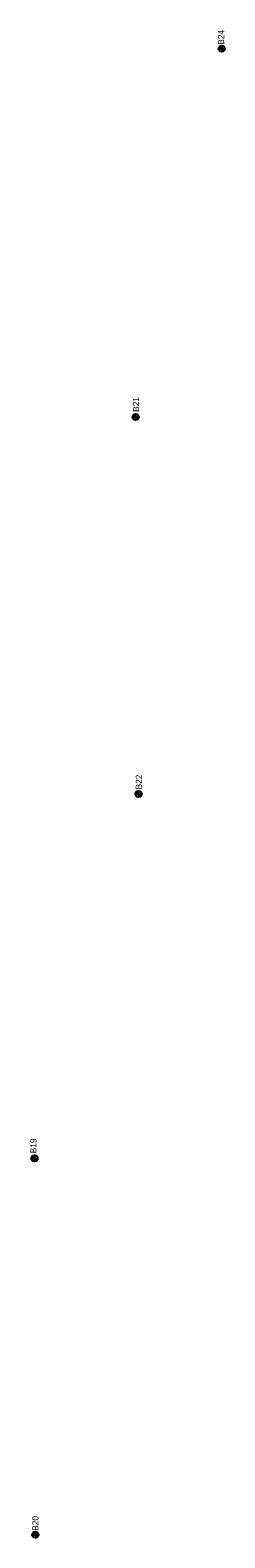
# Model space of a CAD drawing. Extents: x 331323 to 388339, y 121519 to 205315.
# Drawn here: x 361288 to 361600, y 138551 to 140969 of the extents above; entities that cross this region are included whole.
import ezdxf

# ---------------------------------------------------------------- set-up
doc = ezdxf.new("R2010")
doc.units = 0
for name, color, linetype in [('E_SOIL_BORE1 [KAPUR_CADDS_LEVELS]', 7, 'Continuous'), ('E_SOIL_BORE2 [KAPUR_CADDS_LEVELS]', 7, 'Continuous'), ('P_MARK', 7, 'Continuous')]:
    doc.layers.add(name, color=color, linetype=linetype)

msp = doc.modelspace()

# ---------------------------------------------------------------- linework, layer by layer
at = {"layer": 'P_MARK'}
for p, q in [((361590.2, 140939.4), (361600.2, 140939.3)), ((361595.2, 140944.3), (361595.2, 140934.4)), ((361452.1, 140348.7), (361462, 140348.7)), ((361457.1, 140353.7), (361457, 140343.7)), ((361456.7, 139744.2), (361466.7, 139744.2)), ((361461.7, 139749.2), (361461.7, 139739.2)), ((361289.9, 139159.7), (361299.9, 139159.7)), ((361294.9, 139164.7), (361294.9, 139154.7)), ((361291.3, 138556.1), (361301.3, 138556.1)), ((361296.3, 138561.1), (361296.3, 138551.1))]:
    msp.add_line(p, q, dxfattribs=at)
for centre in [(361595.2, 140939.4), (361457.1, 140348.7), (361461.7, 139744.2), (361294.9, 139159.7), (361296.3, 138556.1)]:
    msp.add_circle(centre, 5, dxfattribs=at)
for centre, radius, start, end in [((361595.2, 140939.4), 4.5, 89.9869, 179.9869), ((361595.2, 140939.4), 4, 89.9869, 179.9869), ((361595.2, 140939.4), 3.5, 89.9869, 179.9869), ((361595.2, 140939.4), 3, 89.9869, 179.9869), ((361595.2, 140939.4), 2.5, 89.9869, 179.9869), ((361595.2, 140939.4), 2, 89.9869, 179.9869), ((361595.2, 140939.4), 1.5, 89.9869, 179.9869), ((361595.2, 140939.4), 1, 89.9869, 179.9869), ((361595.2, 140939.4), 0.5, 89.9869, 179.9869), ((361595.2, 140939.4), 4.5, 269.9869, 359.9869), ((361595.2, 140939.4), 4, 269.9869, 359.9869), ((361595.2, 140939.4), 3.5, 269.9869, 359.9869), ((361595.2, 140939.4), 3, 269.9869, 359.9869), ((361595.2, 140939.4), 2.5, 269.9869, 359.9869), ((361595.2, 140939.4), 2, 269.9869, 359.9869), ((361595.2, 140939.4), 1.5, 269.9869, 359.9869), ((361595.2, 140939.4), 1, 269.9869, 359.9869), ((361595.2, 140939.4), 0.5, 269.9869, 359.9869), ((361457.1, 140348.7), 4.5, 89.9869, 179.9869), ((361457.1, 140348.7), 4, 89.9869, 179.9869), ((361457.1, 140348.7), 3.5, 89.9869, 179.9869), ((361457.1, 140348.7), 3, 89.9869, 179.9869), ((361457.1, 140348.7), 2.5, 89.9869, 179.9869), ((361457.1, 140348.7), 2, 89.9869, 179.9869), ((361457.1, 140348.7), 1.5, 89.9869, 179.9869), ((361457.1, 140348.7), 1, 89.9869, 179.9869), ((361457.1, 140348.7), 0.5, 89.9869, 179.9869), ((361457.1, 140348.7), 4.5, 269.9869, 359.9869), ((361457.1, 140348.7), 4, 269.9869, 359.9869), ((361457.1, 140348.7), 3.5, 269.9869, 359.9869), ((361457.1, 140348.7), 3, 269.9869, 359.9869), ((361457.1, 140348.7), 2.5, 269.9869, 359.9869), ((361457.1, 140348.7), 2, 269.9869, 359.9869), ((361457.1, 140348.7), 1.5, 269.9869, 359.9869), ((361457.1, 140348.7), 1, 269.9869, 359.9869), ((361457.1, 140348.7), 0.5, 269.9869, 359.9869), ((361461.7, 139744.2), 4.5, 89.9869, 179.9869), ((361461.7, 139744.2), 4, 89.9869, 179.9869), ((361461.7, 139744.2), 3.5, 89.9869, 179.9869), ((361461.7, 139744.2), 3, 89.9869, 179.9869), ((361461.7, 139744.2), 2.5, 89.9869, 179.9869), ((361461.7, 139744.2), 2, 89.9869, 179.9869), ((361461.7, 139744.2), 1.5, 89.9869, 179.9869), ((361461.7, 139744.2), 1, 89.9869, 179.9869), ((361461.7, 139744.2), 0.5, 89.9869, 179.9869), ((361461.7, 139744.2), 4.5, 269.9869, 359.9869), ((361461.7, 139744.2), 4, 269.9869, 359.9869), ((361461.7, 139744.2), 3.5, 269.9869, 359.9869), ((361461.7, 139744.2), 3, 269.9869, 359.9869), ((361461.7, 139744.2), 2.5, 269.9869, 359.9869), ((361461.7, 139744.2), 2, 269.9869, 359.9869), ((361461.7, 139744.2), 1.5, 269.9869, 359.9869), ((361461.7, 139744.2), 1, 269.9869, 359.9869), ((361461.7, 139744.2), 0.5, 269.9869, 359.9869), ((361294.9, 139159.7), 4.5, 89.9869, 179.9869), ((361294.9, 139159.7), 4, 89.9869, 179.9869), ((361294.9, 139159.7), 3.5, 89.9869, 179.9869), ((361294.9, 139159.7), 3, 89.9869, 179.9869), ((361294.9, 139159.7), 2.5, 89.9869, 179.9869), ((361294.9, 139159.7), 2, 89.9869, 179.9869), ((361294.9, 139159.7), 1.5, 89.9869, 179.9869), ((361294.9, 139159.7), 1, 89.9869, 179.9869), ((361294.9, 139159.7), 0.5, 89.9869, 179.9869), ((361294.9, 139159.7), 4.5, 269.9869, 359.9869), ((361294.9, 139159.7), 4, 269.9869, 359.9869), ((361294.9, 139159.7), 3.5, 269.9869, 359.9869), ((361294.9, 139159.7), 3, 269.9869, 359.9869), ((361294.9, 139159.7), 2.5, 269.9869, 359.9869), ((361294.9, 139159.7), 2, 269.9869, 359.9869), ((361294.9, 139159.7), 1.5, 269.9869, 359.9869), ((361294.9, 139159.7), 1, 269.9869, 359.9869), ((361294.9, 139159.7), 0.5, 269.9869, 359.9869), ((361296.3, 138556.1), 4.5, 89.9869, 179.9869), ((361296.3, 138556.1), 4, 89.9869, 179.9869), ((361296.3, 138556.1), 3.5, 89.9869, 179.9869), ((361296.3, 138556.1), 3, 89.9869, 179.9869), ((361296.3, 138556.1), 2.5, 89.9869, 179.9869), ((361296.3, 138556.1), 2, 89.9869, 179.9869), ((361296.3, 138556.1), 1.5, 89.9869, 179.9869), ((361296.3, 138556.1), 1, 89.9869, 179.9869), ((361296.3, 138556.1), 0.5, 89.9869, 179.9869), ((361296.3, 138556.1), 4.5, 269.9869, 359.9869), ((361296.3, 138556.1), 4, 269.9869, 359.9869), ((361296.3, 138556.1), 3.5, 269.9869, 359.9869), ((361296.3, 138556.1), 3, 269.9869, 359.9869), ((361296.3, 138556.1), 2.5, 269.9869, 359.9869), ((361296.3, 138556.1), 2, 269.9869, 359.9869), ((361296.3, 138556.1), 1.5, 269.9869, 359.9869), ((361296.3, 138556.1), 1, 269.9869, 359.9869), ((361296.3, 138556.1), 0.5, 269.9869, 359.9869)]:
    msp.add_arc(centre, radius, start, end, dxfattribs=at)

# ---------------------------------------------------------------- texts
at = {"layer": 'E_SOIL_BORE1 [KAPUR_CADDS_LEVELS]'}
for s, p in [('B24', (361599.1, 140945.7)), ('B20', (361301.3, 138562.4))]:
    msp.add_text(s, height=10, rotation=89.9869, dxfattribs=at).set_placement(p)
at = {"layer": 'E_SOIL_BORE2 [KAPUR_CADDS_LEVELS]'}
for s, p in [('B21', (361462.7, 140356.9)), ('B22', (361467.2, 139751.4)), ('B19', (361298.1, 139167.9))]:
    msp.add_text(s, height=10, rotation=89.9869, dxfattribs=at).set_placement(p)

doc.saveas('drawing.dxf')
